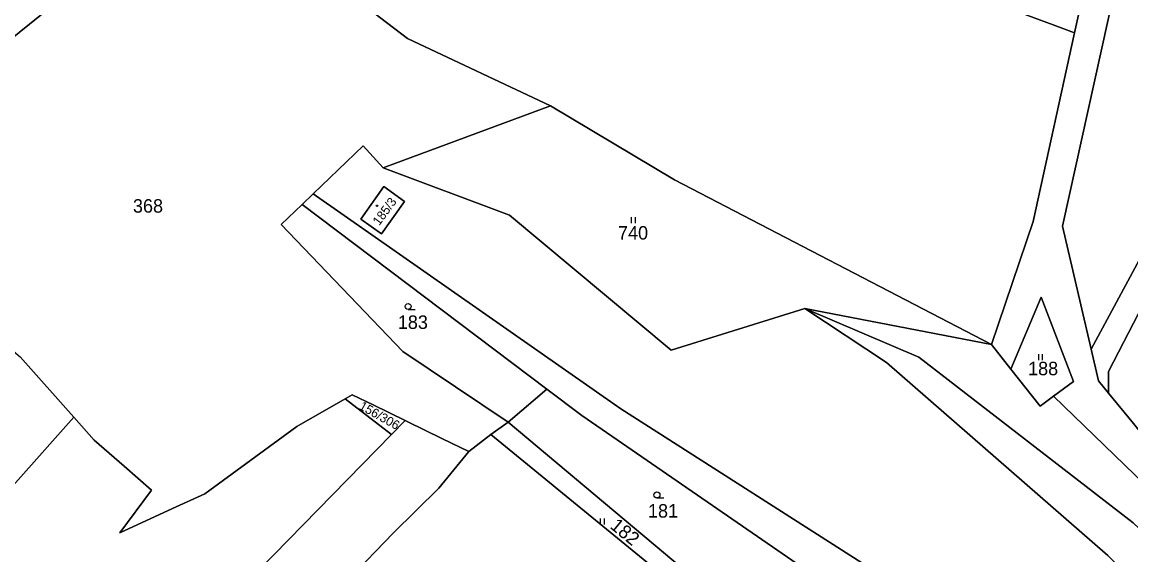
# Model space of a CAD drawing. Extents: x -598233 to -596890, y -1157848 to -1156431.
# Drawn here: x -597630.6 to -597490.9, y -1156606.5 to -1156539.3 of the extents above; entities that cross this region are included whole.
import ezdxf

# ---------------------------------------------------------------- set-up
doc = ezdxf.new("R2010")
doc.units = 0
for name, color, linetype in [('Level 1', 7, 'Continuous'), ('Level 4', 7, 'Continuous'), ('Level 5', 7, 'Continuous'), ('Level 60', 7, 'Continuous'), ('Vrstva 60', 7, 'Continuous')]:
    doc.layers.add(name, color=color, linetype=linetype)

msp = doc.modelspace()

# ---------------------------------------------------------------- linework, layer by layer
at = {"layer": 'Level 1'}
for points in [[(-597450.93, -1156497.14), (-597465.28, -1156523.77), (-597475.86, -1156543.4), (-597495.88, -1156580.52)], [(-597608.92, -1156520.79), (-597622.74, -1156533.93), (-597633.83, -1156542.88), (-597660.84, -1156556.14)], [(-597564, -1156549.84), (-597582.01, -1156541.36), (-597608.92, -1156520.79)], [(-597495.88, -1156580.52), (-597499.49, -1156565.04), (-597489.73, -1156520.84)], [(-597453.92, -1156523.93), (-597460.44, -1156520.44), (-597473.66, -1156544.59), (-597493.7, -1156583.36), (-597493.66, -1156586.09)], [(-597494.56, -1156525.2), (-597497.95, -1156540.64)], [(-597508.31, -1156536.82), (-597500.66, -1156539.64), (-597497.95, -1156540.64)], [(-597508.43, -1156579.93), (-597503.16, -1156564.42), (-597497.95, -1156540.64)], [(-597585.1, -1156557.68), (-597564, -1156549.84)], [(-597564, -1156549.84), (-597548.39, -1156559.19), (-597508.43, -1156579.93)], [(-597593.91, -1156560.96), (-597587.63, -1156554.89), (-597585.1, -1156557.68)], [(-597585.1, -1156557.68), (-597569.16, -1156563.62), (-597548.81, -1156580.65), (-597531.96, -1156575.39)], [(-597585.02, -1156560.04), (-597587.92, -1156564.12), (-597585.31, -1156565.97), (-597582.41, -1156561.9), (-597585.02, -1156560.04)], [(-597593.91, -1156560.96), (-597595.32, -1156562.3)], [(-597387.1, -1156750.16), (-597404.01, -1156722.88), (-597415.25, -1156708.47), (-597463.57, -1156657.36), (-597504.56, -1156622.97), (-597521.75, -1156609.41), (-597555.14, -1156588.05), (-597593.91, -1156560.96)], [(-597595.32, -1156562.3), (-597597.97, -1156564.83), (-597582.6, -1156580.83), (-597569.33, -1156589.73)], [(-597564.47, -1156585.58), (-597595.32, -1156562.3)], [(-597644.2, -1156570.12), (-597630.83, -1156581.48), (-597624.08, -1156589.12)], [(-597505.97, -1156583.05), (-597502.17, -1156573.98), (-597498.08, -1156584.61), (-597500.6, -1156586.46)], [(-597368.34, -1156746.93), (-597381.27, -1156729.71), (-597402.11, -1156696.58), (-597409.53, -1156686.42), (-597413, -1156671.49), (-597424.04, -1156653.42), (-597435.65, -1156640.59), (-597445.88, -1156634.28), (-597459.81, -1156629.4), (-597470.61, -1156627.66), (-597477.64, -1156623), (-597493.75, -1156606.54), (-597521.64, -1156582.22), (-597531.96, -1156575.39)], [(-597368.34, -1156746.93), (-597378.19, -1156728.27), (-597396.68, -1156694.03), (-597403.55, -1156683.62), (-597407.66, -1156668.99), (-597420.72, -1156649.16), (-597432.95, -1156637.12), (-597443.12, -1156630.73), (-597456.62, -1156625.29), (-597466.39, -1156622.46), (-597473.9, -1156618.19), (-597490.56, -1156602.44), (-597517.59, -1156581.52), (-597531.96, -1156575.39)], [(-597508.43, -1156579.93), (-597531.96, -1156575.39)], [(-597505.97, -1156583.05), (-597508.43, -1156579.93)], [(-597493.66, -1156586.09), (-597494.94, -1156584.54), (-597495.88, -1156580.52)], [(-597500.6, -1156586.46), (-597502.3, -1156587.7), (-597505.97, -1156583.05)], [(-597589.89, -1156586.8), (-597589, -1156586.29), (-597586.37, -1156587.57), (-597582.33, -1156589.54)], [(-597569.33, -1156589.73), (-597564.47, -1156585.58)], [(-597532.93, -1156607.58), (-597560.07, -1156588.9), (-597564.47, -1156585.58)], [(-597367.44, -1156730.11), (-597397.92, -1156674.2), (-597409.74, -1156653.7), (-597430.7, -1156634.47), (-597462.43, -1156617.98), (-597487.78, -1156598.86), (-597500.6, -1156586.46)], [(-597493.66, -1156586.09), (-597490.54, -1156589.9), (-597489.85, -1156590.73)], [(-597589.89, -1156586.8), (-597595.98, -1156590.28), (-597607.56, -1156598.76), (-597611.63, -1156600.63), (-597618.29, -1156603.68), (-597614.27, -1156598.32), (-597617.74, -1156595.3), (-597621.52, -1156592.01), (-597624.08, -1156589.12)], [(-597584.04, -1156591.29), (-597589.89, -1156586.8)], [(-597624.08, -1156589.12), (-597651.52, -1156619.94)], [(-597582.33, -1156589.54), (-597584.04, -1156591.29)], [(-597574.28, -1156593.45), (-597577.69, -1156591.79), (-597582, -1156589.7), (-597582.33, -1156589.54)], [(-597569.33, -1156589.73), (-597571.53, -1156591.29)], [(-597569.33, -1156589.73), (-597538.82, -1156615.39)], [(-597584.04, -1156591.29), (-597630.41, -1156638.74)], [(-597571.53, -1156591.29), (-597574.28, -1156593.45)], [(-597571.53, -1156591.29), (-597540.08, -1156617.07)], [(-597574.28, -1156593.45), (-597578.07, -1156598.05), (-597583.83, -1156603.74), (-597589.41, -1156609.52)]]:
    msp.add_lwpolyline(points, dxfattribs=at)
at = {"layer": 'Level 5'}
for p, q in [((-597553.81, -1156564.66), (-597553.81, -1156563.9)), ((-597553.31, -1156564.66), (-597553.31, -1156563.9)), ((-597581.95, -1156575.53), (-597581.08, -1156575.53)), ((-597502.48, -1156581.92), (-597502.48, -1156581.16)), ((-597501.98, -1156581.92), (-597501.98, -1156581.16)), ((-597550.59, -1156599.29), (-597549.71, -1156599.29)), ((-597557.72, -1156602.62), (-597557.72, -1156601.87)), ((-597557.22, -1156602.62), (-597557.22, -1156601.87))]:
    msp.add_line(p, q, dxfattribs=at)
for centre, radius in [((-597585.87, -1156562.45), 0.09), ((-597585.87, -1156562.45), 0.0521), ((-597581.95, -1156575.15), 0.375), ((-597550.59, -1156598.91), 0.375)]:
    msp.add_circle(centre, radius, dxfattribs=at)
at = {"layer": 'Level 60'}
for points in [[(-597439.73, -1156476.36), (-597434.2, -1156466.33), (-597425.34, -1156470.7), (-597453.92, -1156523.93), (-597460.44, -1156520.44), (-597473.66, -1156544.59), (-597493.7, -1156583.36), (-597493.66, -1156586.09), (-597494.94, -1156584.54), (-597495.88, -1156580.52), (-597475.86, -1156543.4), (-597465.28, -1156523.77), (-597450.93, -1156497.14)], [(-597495.88, -1156580.52), (-597499.49, -1156565.04), (-597489.73, -1156520.84), (-597475.78, -1156506.26), (-597464.21, -1156493.96), (-597463.47, -1156494.14), (-597450.93, -1156497.14), (-597465.28, -1156523.77), (-597475.86, -1156543.4)], [(-597494.89, -1156511.66), (-597494.5, -1156514.63), (-597494.56, -1156525.2), (-597497.95, -1156540.64), (-597500.66, -1156539.64), (-597508.31, -1156536.82), (-597506.37, -1156501.83), (-597501.41, -1156503.3), (-597505.8, -1156503.05), (-597506.04, -1156507.09), (-597501.64, -1156507.34), (-597501.41, -1156503.3), (-597496.95, -1156504.63)], [(-597453.92, -1156523.93), (-597446.74, -1156527.77), (-597451.35, -1156536.46), (-597457.69, -1156532.94), (-597489.85, -1156590.73), (-597490.54, -1156589.9), (-597493.66, -1156586.09), (-597493.7, -1156583.36), (-597473.66, -1156544.59), (-597460.44, -1156520.44)], [(-597569.16, -1156563.62), (-597585.1, -1156557.68), (-597564, -1156549.84), (-597548.39, -1156559.19), (-597508.43, -1156579.93), (-597531.96, -1156575.39), (-597548.81, -1156580.65)], [(-597587.92, -1156564.12), (-597585.02, -1156560.04), (-597582.41, -1156561.9), (-597585.31, -1156565.97)], [(-597585.02, -1156560.04), (-597587.92, -1156564.12), (-597585.31, -1156565.97), (-597582.41, -1156561.9)], [(-597595.32, -1156562.3), (-597564.47, -1156585.58), (-597569.33, -1156589.73), (-597582.6, -1156580.83), (-597597.97, -1156564.83)], [(-597660.92, -1156611.57), (-597674.65, -1156599.34), (-597644.2, -1156570.12), (-597630.83, -1156581.48), (-597624.08, -1156589.12), (-597651.52, -1156619.94)], [(-597500.6, -1156586.46), (-597502.3, -1156587.7), (-597505.97, -1156583.05), (-597502.17, -1156573.98), (-597498.08, -1156584.61)], [(-597368.34, -1156746.93), (-597378.19, -1156728.27), (-597396.68, -1156694.03), (-597403.55, -1156683.62), (-597407.66, -1156668.99), (-597420.72, -1156649.16), (-597432.95, -1156637.12), (-597443.12, -1156630.73), (-597456.62, -1156625.29), (-597466.39, -1156622.46), (-597473.9, -1156618.19), (-597490.56, -1156602.44), (-597517.59, -1156581.52), (-597531.96, -1156575.39), (-597508.43, -1156579.93), (-597505.97, -1156583.05), (-597502.3, -1156587.7), (-597500.6, -1156586.46), (-597487.78, -1156598.86), (-597462.43, -1156617.98), (-597430.7, -1156634.47), (-597409.74, -1156653.7), (-597397.92, -1156674.2), (-597367.44, -1156730.11)], [(-597584.04, -1156591.29), (-597589.89, -1156586.8), (-597589, -1156586.29), (-597586.37, -1156587.57), (-597582.33, -1156589.54)], [(-597560.07, -1156588.9), (-597532.93, -1156607.58), (-597538.82, -1156615.39), (-597569.33, -1156589.73), (-597564.47, -1156585.58)], [(-597651.52, -1156619.94), (-597624.08, -1156589.12), (-597621.52, -1156592.01), (-597617.74, -1156595.3), (-597614.27, -1156598.32), (-597618.29, -1156603.68), (-597611.63, -1156600.63), (-597607.56, -1156598.76), (-597595.98, -1156590.28), (-597589.89, -1156586.8), (-597584.04, -1156591.29), (-597630.41, -1156638.74), (-597638.46, -1156631.57), (-597649.76, -1156621.51)], [(-597574.28, -1156593.45), (-597578.07, -1156598.05), (-597583.83, -1156603.74), (-597589.41, -1156609.52), (-597595.28, -1156615.72), (-597616.82, -1156637.92), (-597624, -1156645.06), (-597630.41, -1156638.74), (-597584.04, -1156591.29), (-597582.33, -1156589.54), (-597582, -1156589.7), (-597577.69, -1156591.79)], [(-597540.08, -1156617.07), (-597571.53, -1156591.29), (-597569.33, -1156589.73), (-597538.82, -1156615.39)]]:
    msp.add_lwpolyline(points, close=True, dxfattribs=at)
for points in [[(-597487.78, -1156598.86), (-597500.6, -1156586.46), (-597498.08, -1156584.61), (-597502.17, -1156573.98), (-597505.97, -1156583.05), (-597508.43, -1156579.93), (-597503.16, -1156564.42), (-597497.95, -1156540.64), (-597494.56, -1156525.2), (-597493.12, -1156518.61), (-597491.67, -1156517.9), (-597489.37, -1156516.99)], [(-597608.92, -1156520.79), (-597582.01, -1156541.36), (-597564, -1156549.84), (-597585.1, -1156557.68), (-597587.63, -1156554.89), (-597593.91, -1156560.96), (-597595.32, -1156562.3), (-597597.97, -1156564.83), (-597582.6, -1156580.83), (-597569.33, -1156589.73), (-597571.53, -1156591.29), (-597574.28, -1156593.45), (-597577.69, -1156591.79), (-597582, -1156589.7), (-597582.33, -1156589.54), (-597586.37, -1156587.57), (-597589, -1156586.29), (-597589.89, -1156586.8), (-597595.98, -1156590.28), (-597607.56, -1156598.76), (-597611.63, -1156600.63), (-597618.29, -1156603.68), (-597614.27, -1156598.32), (-597617.74, -1156595.3), (-597621.52, -1156592.01), (-597624.08, -1156589.12), (-597630.83, -1156581.48)], [(-597508.31, -1156536.82), (-597500.66, -1156539.64), (-597497.95, -1156540.64), (-597503.16, -1156564.42), (-597508.43, -1156579.93), (-597548.39, -1156559.19), (-597564, -1156549.84), (-597582.01, -1156541.36), (-597608.92, -1156520.79)], [(-597489.73, -1156520.84), (-597499.49, -1156565.04), (-597495.88, -1156580.52), (-597494.94, -1156584.54), (-597493.66, -1156586.09), (-597490.54, -1156589.9)], [(-597633.83, -1156542.88), (-597622.74, -1156533.93)], [(-597415.25, -1156708.47), (-597463.57, -1156657.36), (-597504.56, -1156622.97), (-597521.75, -1156609.41), (-597555.14, -1156588.05), (-597593.91, -1156560.96), (-597587.63, -1156554.89), (-597585.1, -1156557.68), (-597569.16, -1156563.62), (-597548.81, -1156580.65), (-597531.96, -1156575.39), (-597521.64, -1156582.22), (-597493.75, -1156606.54), (-597477.64, -1156623), (-597470.61, -1156627.66), (-597459.81, -1156629.4), (-597445.88, -1156634.28), (-597435.65, -1156640.59), (-597424.04, -1156653.42), (-597413, -1156671.49), (-597409.53, -1156686.42), (-597402.11, -1156696.58)], [(-597418.31, -1156709.94), (-597450.91, -1156674.87), (-597473.3, -1156654.31), (-597485.83, -1156643.7), (-597507.42, -1156625.94), (-597524.74, -1156613.03), (-597532.93, -1156607.58), (-597560.07, -1156588.9), (-597564.47, -1156585.58), (-597595.32, -1156562.3), (-597593.91, -1156560.96), (-597555.14, -1156588.05), (-597521.75, -1156609.41), (-597504.56, -1156622.97), (-597463.57, -1156657.36), (-597415.25, -1156708.47)], [(-597402.11, -1156696.58), (-597409.53, -1156686.42), (-597413, -1156671.49), (-597424.04, -1156653.42), (-597435.65, -1156640.59), (-597445.88, -1156634.28), (-597459.81, -1156629.4), (-597470.61, -1156627.66), (-597477.64, -1156623), (-597493.75, -1156606.54), (-597521.64, -1156582.22), (-597531.96, -1156575.39), (-597517.59, -1156581.52), (-597490.56, -1156602.44), (-597473.9, -1156618.19), (-597466.39, -1156622.46), (-597456.62, -1156625.29), (-597443.12, -1156630.73), (-597432.95, -1156637.12), (-597420.72, -1156649.16), (-597407.66, -1156668.99), (-597403.55, -1156683.62), (-597396.68, -1156694.03), (-597378.19, -1156728.27)], [(-597477.08, -1156710.21), (-597509.25, -1156678.1), (-597519.29, -1156668.68), (-597551.75, -1156641.97), (-597589.41, -1156609.52), (-597583.83, -1156603.74), (-597578.07, -1156598.05), (-597574.28, -1156593.45), (-597571.53, -1156591.29), (-597540.08, -1156617.07), (-597517.49, -1156636.94), (-597498, -1156655.42), (-597479.27, -1156674.01), (-597464.34, -1156687.53), (-597432.83, -1156721.56)]]:
    msp.add_lwpolyline(points, dxfattribs=at)
at = {"layer": 'Vrstva 60'}
msp.add_lwpolyline([(-597728.53, -1156519.44), (-597710.3, -1156515.63), (-597679.72, -1156538.87), (-597674.19, -1156544.27), (-597669.38, -1156550.28), (-597660.84, -1156556.14), (-597633.83, -1156542.88), (-597622.74, -1156533.93), (-597608.92, -1156520.79), (-597612.57, -1156518), (-597639.9, -1156495.95), (-597650.81, -1156484.34), (-597653.34, -1156483.9), (-597664.9, -1156481.89), (-597669.04, -1156478.62), (-597671.13, -1156480.96), (-597694.63, -1156462.22), (-597705.48, -1156446.85), (-597722.59, -1156430.86)], dxfattribs=at)

# ---------------------------------------------------------------- texts
at = {"layer": 'Level 4'}
for s, height, rotation, p in [('185/3', 1.14, 53.7147, (-597585.59, -1156565.02)), ('156/306', 1.14, 330.5241, (-597588.23, -1156588.03)), ('182', 1.7, 320.5567, (-597556.61, -1156603.01))]:
    msp.add_text(s, height=height, rotation=rotation, dxfattribs=at).set_placement(p)
for s, p in [('368', (-597616.63, -1156563.32)), ('740', (-597555.5, -1156566.71)), ('183', (-597583.25, -1156577.98)), ('188', (-597503.82, -1156583.82)), ('181', (-597551.72, -1156601.77))]:
    msp.add_text(s, height=1.7, dxfattribs=at).set_placement(p)

doc.saveas('drawing.dxf')
